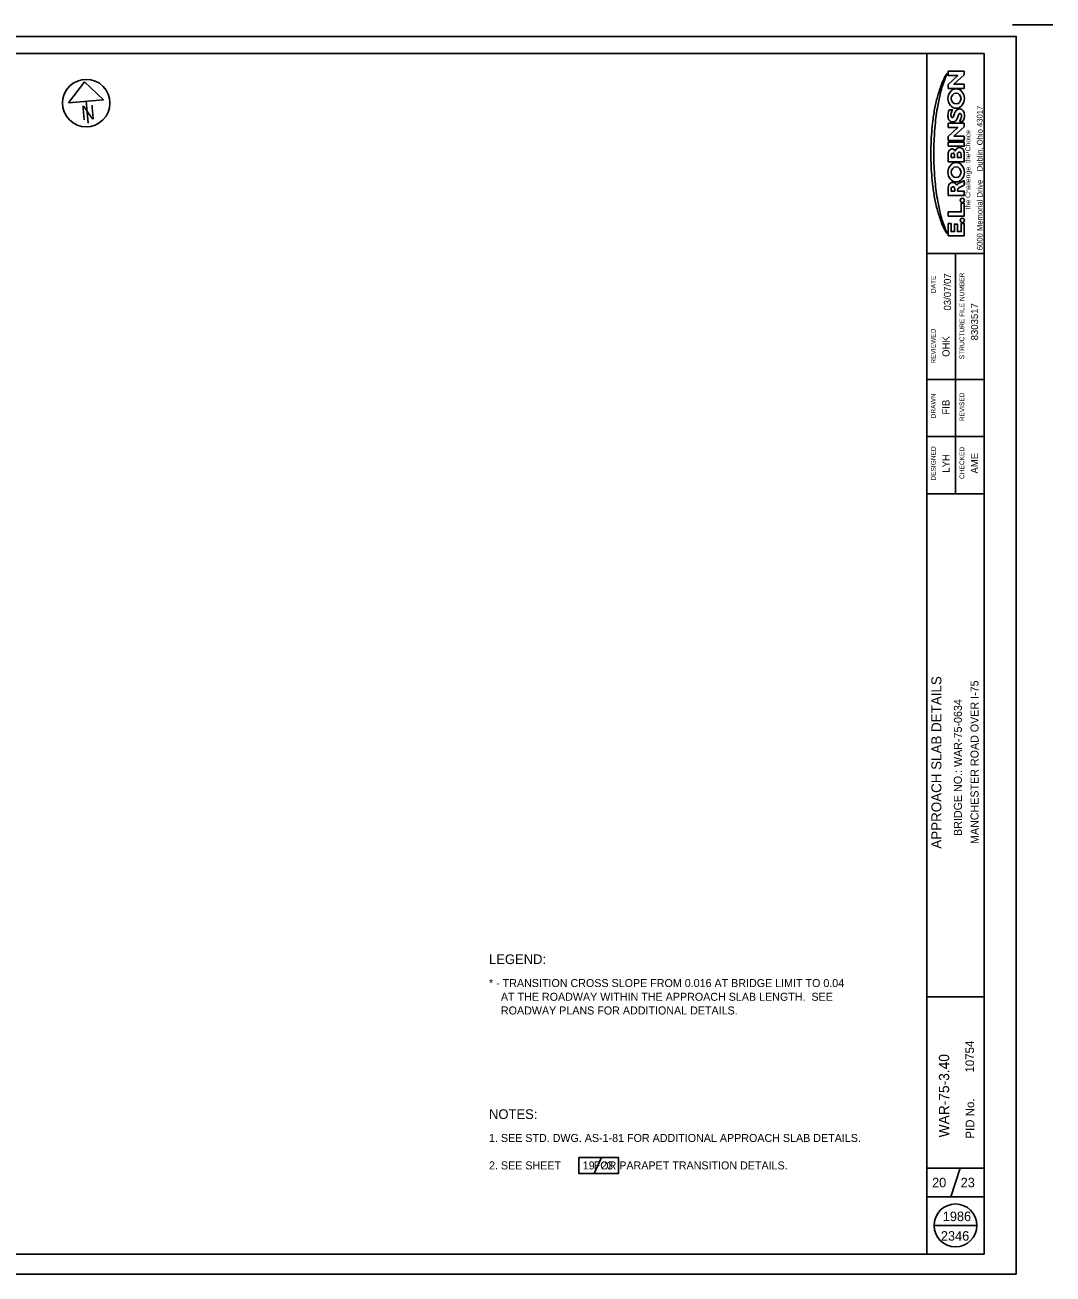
# Model space of a CAD drawing. Extents: x 104.8 to 140.7, y 4.6 to 26.6.
# Drawn here: x 122.74 to 140.72, y 4.7 to 26.55 of the extents above; entities that cross this region are included whole.
import ezdxf

# ---------------------------------------------------------------- set-up
doc = ezdxf.new("R2010")
doc.units = 0
for name, color, linetype in [('BR_P_Gen_Text', 7, 'Continuous'), ('SH_Border', 7, 'Continuous'), ('SH_Cut_Line', 7, 'Continuous'), ('SH_Data', 7, 'Continuous')]:
    doc.layers.add(name, color=color, linetype=linetype)

msp = doc.modelspace()

# ---------------------------------------------------------------- linework, layer by layer
at = {"layer": 'BR_P_Gen_Text'}
for p, q in [((139.143, 24.862), (139.082, 24.862)), ((139.082, 24.862), (139.143, 24.862)), ((138.887, 24.159), (138.887, 24.294)), ((138.938, 24.279), (138.938, 24.234)), ((138.938, 24.234), (138.938, 24.279)), ((139.166, 24.309), (139.166, 24.159)), ((139.166, 24.159), (138.887, 24.159)), ((138.937, 23.689), (138.937, 23.646)), ((138.937, 23.646), (138.937, 23.689)), ((138.937, 23.646), (139.001, 23.646)), ((139.001, 23.646), (138.937, 23.646)), ((139.001, 23.646), (139.001, 23.689)), ((139.001, 23.689), (139.001, 23.646)), ((139.166, 23.749), (139.084, 23.71)), ((139.084, 23.71), (139.166, 23.749)), ((132.824, 6.741), (132.695, 6.463))]:
    msp.add_line(p, q, dxfattribs=at)
for points in [[(139.166, 25.443), (138.887, 25.443), (138.887, 25.512), (139.055, 25.668), (138.887, 25.668), (138.887, 25.743), (139.166, 25.743), (139.166, 25.678), (138.988, 25.517), (139.166, 25.517)], [(139.166, 24.535), (138.887, 24.535), (138.887, 24.604), (139.055, 24.76), (138.887, 24.76), (138.887, 24.834), (139.166, 24.834), (139.166, 24.77), (138.988, 24.609), (139.166, 24.609)], [(138.887, 24.431), (138.887, 24.505), (139.166, 24.505), (139.166, 24.431)], [(138.887, 22.863), (138.887, 23.078), (138.938, 23.078), (138.938, 22.939), (138.996, 22.939), (138.996, 23.07), (139.047, 23.07), (139.047, 22.939), (139.114, 22.939), (139.114, 23.081), (139.166, 23.081), (139.166, 22.863)], [(132.427, 6.741), (133.123, 6.741), (133.123, 6.463), (132.427, 6.463)], [(132.427, 6.741), (133.123, 6.741), (133.123, 6.463), (132.427, 6.463)]]:
    msp.add_lwpolyline(points, close=True, dxfattribs=at)
for points in [[(138.905, 25.07), (138.96, 25.07), (138.949, 25.043)], [(138.949, 25.043), (138.96, 25.07), (138.905, 25.07)], [(139.166, 24.309), (139.166, 24.159), (138.887, 24.159), (138.887, 24.294)], [(138.887, 24.294), (138.887, 24.159), (139.166, 24.159)], [(138.938, 24.234), (138.997, 24.234), (138.997, 24.279)], [(138.997, 24.279), (138.997, 24.234), (138.938, 24.234)], [(139.048, 24.288), (139.048, 24.234), (139.114, 24.234), (139.114, 24.288)], [(139.114, 24.288), (139.114, 24.234), (139.048, 24.234), (139.048, 24.288)], [(139.166, 24.159), (139.166, 24.309)], [(139.101, 23.799), (139.166, 23.831), (139.166, 23.749)], [(139.166, 23.749), (139.166, 23.831), (139.101, 23.799)], [(139.052, 23.668), (139.052, 23.646), (139.166, 23.646), (139.166, 23.571), (138.887, 23.571), (138.887, 23.646), (138.887, 23.71)], [(138.887, 23.71), (138.887, 23.646), (138.887, 23.571), (139.166, 23.571)], [(138.937, 23.689), (138.937, 23.646), (139.001, 23.646), (139.001, 23.689)], [(139.166, 23.571), (139.166, 23.646), (139.052, 23.646), (139.052, 23.668)], [(138.887, 23.207), (138.887, 23.282), (139.114, 23.282), (139.114, 23.434), (139.166, 23.434), (139.166, 23.207), (138.887, 23.207)], [(139.166, 23.434), (139.114, 23.434), (139.114, 23.282), (138.887, 23.282), (138.887, 23.207)], [(138.887, 23.207), (139.166, 23.207), (139.166, 23.434)]]:
    msp.add_lwpolyline(points, dxfattribs=at)
for centre, major_axis, ratio, start_param, end_param in [((140.128, 24.895), (0, 1.685), 0.85, 1.132502, 1.288747), ((140.128, 24.895), (0, 1.685), 0.85, 1.132502, 1.288747), ((139.65, 25.036), (0, 1.141), 0.85, 0.988431, 1.105191), ((139.65, 25.036), (0, 1.141), 0.85, 0.988431, 1.105191), ((100.385, 46.81), (0, 49.953), 0.85, 4.274094, 4.276309), ((100.385, 46.81), (0, 49.953), 0.85, 4.274094, 4.276309), ((139.097, 25.464), (0, 0.363), 0.85, 0.822588, 0.988431), ((139.097, 25.464), (0, 0.363), 0.85, 0.822588, 0.988431), ((141.626, 24.385), (0, 3.52), 0.85, 1.288747, 1.354281), ((141.626, 24.385), (0, 3.52), 0.85, 1.288747, 1.354281), ((141.202, 24.29), (0, 3.112), 0.85, 1.165908, 1.233316), ((141.202, 24.29), (0, 3.112), 0.85, 1.165908, 1.233316), ((139.226, 25.286), (0, 0.583), 0.85, 1.105191, 1.165908), ((139.226, 25.286), (0, 0.583), 0.85, 1.105191, 1.165908), ((140.411, 24.638), (0, 2.119), 0.85, 1.243005, 1.347881), ((140.411, 24.638), (0, 2.119), 0.85, 1.243005, 1.347881), ((142.845, 24.191), (0, 4.963), 0.85, 1.378198, 1.448475), ((142.845, 24.191), (0, 4.963), 0.85, 1.378198, 1.448475), ((139.026, 25.266), (0, -0.0938), 0.910305, 4.71238898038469, 4.712389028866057), ((141.6, 24.368), (0, 3.544), 0.85, 1.360764, 1.426378), ((141.6, 24.368), (0, 3.544), 0.85, 1.360764, 1.426378), ((139.044, 24.97), (0, 0.19), 0.85, 1.320154, 1.737094), ((139.044, 24.97), (0, 0.19), 0.85, 1.320154, 1.737094), ((138.977, 24.957), (0, 0.11), 0.85, 1.737094, 2.325359), ((138.977, 24.957), (0, 0.11), 0.85, 1.737094, 2.325359), ((139.057, 24.967), (0, 0.206), 0.85, 1.108668, 1.320154), ((139.057, 24.967), (0, 0.206), 0.85, 1.108668, 1.320154), ((138.767, 25.137), (0, 0.176), 0.85, 4.250261, 4.3216), ((138.767, 25.137), (0, 0.176), 0.85, 4.250261, 4.3216), ((139.029, 24.979), (0, 0.111), 0.85, 1.456901, 1.818883), ((139.029, 24.979), (0, 0.111), 0.85, 1.456901, 1.818883), ((139.032, 24.979), (0, 0.115), 0.85, 1.297264, 1.456901), ((139.032, 24.979), (0, 0.115), 0.85, 1.297264, 1.456901), ((138.96, 24.959), (0, 0.0279), 0.85, 1.818883, 2.384672), ((138.96, 24.959), (0, 0.0279), 0.85, 1.818883, 2.384672), ((139.099, 24.957), (0, 0.196), 0.85, 1.114999, 1.297264), ((139.099, 24.957), (0, 0.196), 0.85, 1.114999, 1.297264), ((138.956, 24.953), (0, 0.0197), 0.85, 2.384672, 3.137191), ((138.956, 24.953), (0, 0.0197), 0.85, 2.384672, 3.137191), ((138.956, 24.961), (0, 0.0276), 0.85, 3.137191, 4.01614), ((138.956, 24.961), (0, 0.0276), 0.85, 3.137191, 4.01614), ((138.927, 24.989), (0, 0.071), 0.85, 4.01614, 4.175459), ((138.927, 24.989), (0, 0.071), 0.85, 4.01614, 4.175459), ((138.858, 25.037), (0, 0.165), 0.85, 4.175459, 4.396402), ((138.858, 25.037), (0, 0.165), 0.85, 4.175459, 4.396402), ((139.184, 24.912), (0, 0.238), 0.85, 1.030221, 1.254809), ((139.184, 24.912), (0, 0.238), 0.85, 1.030221, 1.254809), ((139.091, 24.977), (0, 0.11), 0.85, 0.486829, 1.030221), ((139.091, 24.977), (0, 0.11), 0.85, 0.486829, 1.030221), ((138.933, 24.982), (0, 0.145), 0.85, 3.971659, 4.353371), ((138.933, 24.982), (0, 0.145), 0.85, 3.971659, 4.353371), ((139.026, 25.266), (0, -0.17), 0.841969, 0, 4.84813681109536e-08), ((139.077, 25.007), (0, 0.0761), 0.85, 0.083326, 0.486829), ((139.077, 25.007), (0, 0.0761), 0.85, 0.083326, 0.486829), ((139.668, 24.657), (0, 0.778), 0.85, 1.164639, 1.211778), ((139.668, 24.657), (0, 0.778), 0.85, 1.164639, 1.211778), ((139.281, 24.853), (0, 0.284), 0.85, 1.063855, 1.164639), ((139.281, 24.853), (0, 0.284), 0.85, 1.063855, 1.164639), ((139.093, 24.976), (0, 0.0304), 0.85, 0.715581, 1.063855), ((139.093, 24.976), (0, 0.0304), 0.85, 0.715581, 1.063855), ((139.083, 24.93), (0, 0.154), 0.85, 6.083659, 6.366511), ((139.083, 24.93), (0, 0.154), 0.85, 6.083659, 6.366511), ((139.094, 24.975), (0, 0.0317), 0.85, 0.212074, 0.715581), ((139.094, 24.975), (0, 0.0317), 0.85, 0.212074, 0.715581), ((139.093, 24.98), (0, 0.026), 0.85, 5.247627, 6.495259), ((139.093, 24.98), (0, 0.026), 0.85, 5.247627, 6.495259), ((138.827, 25.079), (0, 0.37), 0.85, 4.172563, 4.251833), ((138.827, 25.079), (0, 0.37), 0.85, 4.172563, 4.251833), ((139.096, 25.008), (0, 0.0741), 0.85, 5.529173, 6.083659), ((139.096, 25.008), (0, 0.0741), 0.85, 5.529173, 6.083659), ((139.031, 24.961), (0, 0.103), 0.85, 4.251833, 4.86616), ((139.031, 24.961), (0, 0.103), 0.85, 4.251833, 4.86616), ((139.077, 24.969), (0, 0.0483), 0.85, 4.86616, 5.247627), ((139.077, 24.969), (0, 0.0483), 0.85, 4.86616, 5.247627), ((139.076, 24.983), (0, 0.109), 0.85, 4.887723, 5.529173), ((139.076, 24.983), (0, 0.109), 0.85, 4.887723, 5.529174), ((139.022, 24.959), (0, 0.173), 0.85, 4.318356, 4.51081), ((139.022, 24.959), (0, 0.173), 0.85, 4.318356, 4.51081), ((138.996, 24.966), (0, 0.205), 0.85, 4.51081, 4.887723), ((138.996, 24.966), (0, 0.205), 0.85, 4.51081, 4.887723), ((140.18, 24.545), (0, 1.866), 0.85, 1.391456, 1.496401), ((140.18, 24.545), (0, 1.866), 0.85, 1.391456, 1.496401), ((144.443, 24.124), (0, 6.84), 0.85, 1.472392, 1.505619), ((144.443, 24.124), (0, 6.84), 0.85, 1.472392, 1.505619), ((138.956, 24.934), (0, 0.0764), 0.85, 2.325359, 2.878408), ((138.956, 24.934), (0, 0.0764), 0.85, 2.325359, 2.878408), ((138.964, 24.97), (0, 0.113), 0.85, 2.878408, 3.55749), ((138.964, 24.97), (0, 0.113), 0.85, 2.878408, 3.55749), ((138.978, 24.934), (0, 0.0738), 0.85, 3.55749, 3.971659), ((138.978, 24.934), (0, 0.0738), 0.85, 3.55749, 3.971659), ((138.904, 25.025), (0, 0.265), 0.85, 4.050165, 4.172563), ((138.904, 25.025), (0, 0.265), 0.85, 4.050165, 4.172563), ((139.038, 24.951), (0, 0.152), 0.85, 4.087438, 4.318356), ((139.038, 24.951), (0, 0.152), 0.85, 4.087438, 4.318356), ((140.381, 24.444), (0, 2.111), 0.85, 1.456986, 1.558686), ((140.381, 24.444), (0, 2.111), 0.85, 1.456986, 1.558686), ((141.988, 24.313), (0, 3.944), 0.85, 1.505619, 1.553601), ((141.988, 24.313), (0, 3.944), 0.85, 1.505619, 1.553601), ((142.189, 24.251), (0, 4.243), 0.85, 1.519271, 1.558345), ((142.189, 24.251), (0, 4.243), 0.85, 1.519271, 1.558345), ((142.189, 24.357), (0, 4.243), 0.85, 1.583248, 1.622322), ((142.189, 24.357), (0, 4.243), 0.85, 1.583248, 1.622322), ((140.537, 24.342), (0, 2.237), 0.85, 1.553601, 1.587991), ((140.537, 24.342), (0, 2.237), 0.85, 1.553601, 1.587991), ((140.537, 24.265), (0, 2.237), 0.85, 1.553601, 1.587991), ((140.537, 24.265), (0, 2.237), 0.85, 1.553601, 1.587991), ((138.993, 24.292), (0, 0.124), 0.85, 1.228703, 1.558605), ((138.993, 24.292), (0, 0.124), 0.85, 1.228703, 1.558605), ((138.993, 24.292), (0, 0.124), 0.85, 1.228703, 1.558605), ((138.959, 24.303), (0, 0.0833), 0.85, 0.473795, 1.194239), ((138.959, 24.303), (0, 0.0833), 0.85, 0.473795, 1.194239), ((138.959, 24.303), (0, 0.0833), 0.85, 0.473795, 1.194239), ((138.956, 24.317), (0, 0.0696), 0.85, 5.943917, 6.808987), ((138.956, 24.317), (0, 0.0696), 0.85, 5.943917, 6.808987), ((138.956, 24.317), (0, 0.0696), 0.85, 5.943917, 6.808987), ((138.967, 24.277), (0, 0.0337), 0.85, 6.249041, 7.784024), ((138.967, 24.277), (0, 0.0337), 0.85, 6.249041, 7.784024), ((138.968, 24.277), (0, 0.0337), 0.85, 4.782347, 6.317329), ((138.968, 24.277), (0, 0.0337), 0.85, 4.782347, 6.317329), ((138.954, 24.31), (0, 0.0776), 0.85, 5.231996, 5.947796), ((138.954, 24.31), (0, 0.0776), 0.85, 5.231996, 5.947796), ((138.954, 24.31), (0, 0.0776), 0.85, 5.231996, 5.947795), ((139.084, 24.319), (0, 0.0906), 0.85, 0.462144, 1.247207), ((139.084, 24.319), (0, 0.0906), 0.85, 0.462144, 1.247207), ((139.084, 24.319), (0, 0.0906), 0.85, 0.462144, 1.247207), ((139.082, 24.291), (0, 0.0402), 0.85, 0.503186, 1.629765), ((139.082, 24.291), (0, 0.0402), 0.85, 0.503186, 1.629765), ((139.085, 24.311), (0, 0.0982), 0.85, 6.14188, 6.715345), ((139.085, 24.311), (0, 0.0982), 0.85, 6.14188, 6.715345), ((139.085, 24.311), (0, 0.0982), 0.85, 6.14188, 6.715345), ((139.081, 24.295), (0, 0.0358), 0.85, 6.277029, 6.794667), ((139.081, 24.295), (0, 0.0358), 0.85, 6.277029, 6.794667), ((139.081, 24.295), (0, 0.0358), 0.85, 5.771704, 6.289341), ((139.081, 24.295), (0, 0.0358), 0.85, 5.771704, 6.289341), ((139.08, 24.291), (0, 0.0402), 0.85, 4.65342, 5.779999), ((139.08, 24.291), (0, 0.0402), 0.85, 4.65342, 5.779999), ((139.089, 24.32), (0, 0.0885), 0.85, 5.535543, 6.182102), ((139.089, 24.32), (0, 0.0885), 0.85, 5.535543, 6.182102), ((139.089, 24.32), (0, 0.0885), 0.85, 5.535543, 6.182102), ((139.094, 24.324), (0, 0.0818), 0.85, 4.885157, 5.560215), ((139.094, 24.324), (0, 0.0818), 0.85, 4.885157, 5.560215), ((139.094, 24.324), (0, 0.0818), 0.85, 4.885157, 5.560215), ((138.994, 24.302), (0, 0.202), 0.85, 4.750784, 4.89449), ((138.994, 24.302), (0, 0.202), 0.85, 4.750784, 4.89449), ((138.994, 24.302), (0, 0.202), 0.85, 4.750784, 4.89449), ((140.381, 24.164), (0, 2.111), 0.85, 1.582906, 1.684607), ((140.381, 24.164), (0, 2.111), 0.85, 1.582906, 1.684607), ((141.988, 24.295), (0, 3.944), 0.85, 1.587991, 1.635974), ((141.988, 24.295), (0, 3.944), 0.85, 1.587991, 1.635974), ((144.443, 24.483), (0, 6.84), 0.85, 1.635974, 1.669201), ((144.443, 24.483), (0, 6.84), 0.85, 1.635974, 1.669201), ((140.18, 24.063), (0, 1.866), 0.85, 1.645192, 1.750137), ((140.18, 24.063), (0, 1.866), 0.85, 1.645192, 1.750137), ((139.026, 23.977), (0, -0.0938), 0.910305, 4.71238898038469, 4.712389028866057), ((141.6, 24.24), (0, 3.544), 0.85, 1.715214, 1.780828), ((141.6, 24.24), (0, 3.544), 0.85, 1.715214, 1.780828), ((142.845, 24.417), (0, 4.963), 0.85, 1.693118, 1.763395), ((142.845, 24.417), (0, 4.963), 0.85, 1.693118, 1.763395), ((138.963, 23.709), (0, 0.0895), 0.85, 0.482355, 1.561069), ((138.963, 23.709), (0, 0.0895), 0.85, 0.482355, 1.561069), ((138.968, 23.7), (0, 0.1), 0.85, 6.102437, 6.781247), ((138.968, 23.7), (0, 0.1), 0.85, 6.102437, 6.781247), ((138.977, 23.685), (0, 0.0467), 0.85, 1.002734, 1.50285), ((138.977, 23.685), (0, 0.0467), 0.85, 1.002734, 1.50285), ((138.977, 23.685), (0, 0.0467), 0.85, 1.002734, 1.50285), ((138.968, 23.688), (0, 0.0365), 0.85, 6.259044, 7.205975), ((138.968, 23.688), (0, 0.0365), 0.85, 6.259044, 7.205975), ((138.968, 23.688), (0, 0.0365), 0.85, 6.259044, 7.205975), ((138.97, 23.688), (0, 0.0365), 0.85, 5.360396, 6.307326), ((138.97, 23.688), (0, 0.0365), 0.85, 5.360396, 6.307326), ((138.97, 23.688), (0, 0.0365), 0.85, 5.360396, 6.307326), ((138.967, 23.713), (0, 0.0881), 0.85, 5.152888, 6.061538), ((138.967, 23.713), (0, 0.0881), 0.85, 5.152888, 6.061538), ((138.961, 23.685), (0, 0.0467), 0.85, 4.780335, 5.280452), ((138.961, 23.685), (0, 0.0467), 0.85, 4.780335, 5.280452), ((138.961, 23.685), (0, 0.0467), 0.85, 4.780335, 5.280452), ((139.026, 23.977), (0, -0.17), 0.841969, 0, 4.84813681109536e-08), ((139.085, 23.714), (0, 0.069), 0.85, 0.463729, 1.012038), ((139.085, 23.714), (0, 0.069), 0.85, 0.463729, 1.012038), ((139.078, 23.669), (0, 0.0303), 0.85, 0.984544, 1.600686), ((139.078, 23.669), (0, 0.0303), 0.85, 0.984544, 1.600686), ((139.102, 23.649), (0, 0.0643), 0.85, 0.32473, 0.965239), ((139.102, 23.649), (0, 0.0643), 0.85, 0.32473, 0.965239), ((139.192, 23.502), (0, 0.316), 0.85, 0.346308, 0.520291), ((139.192, 23.502), (0, 0.316), 0.85, 0.346308, 0.520291), ((140.411, 23.969), (0, 2.119), 0.85, 1.793712, 1.898588), ((140.411, 23.969), (0, 2.119), 0.85, 1.793712, 1.898588), ((141.626, 24.223), (0, 3.52), 0.85, 1.787312, 1.852845), ((141.626, 24.223), (0, 3.52), 0.85, 1.787312, 1.852845), ((139.134, 23.484), (0, -0.0377), 0.965476, 4.71238898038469, 4.712389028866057), ((141.202, 24.318), (0, 3.112), 0.85, 1.908276, 1.975684), ((141.202, 24.318), (0, 3.112), 0.85, 1.908276, 1.975684), ((140.128, 23.712), (0, 1.685), 0.85, 1.852845, 2.009091), ((140.128, 23.712), (0, 1.685), 0.85, 1.852845, 2.009091), ((139.226, 23.321), (0, 0.583), 0.85, 1.975684, 2.036401), ((139.226, 23.321), (0, 0.583), 0.85, 1.975684, 2.036401), ((139.65, 23.572), (0, 1.141), 0.85, 2.036401, 2.153161), ((139.65, 23.572), (0, 1.141), 0.85, 2.036401, 2.153161), ((100.385, 1.798), (0, 49.953), 0.85, 5.148469, 5.150684), ((100.385, 1.798), (0, 49.953), 0.85, 5.148469, 5.150684), ((139.097, 23.144), (0, 0.363), 0.85, 2.153161, 2.319004), ((139.097, 23.144), (0, 0.363), 0.85, 2.153161, 2.319004), ((139.134, 23.134), (0, -0.0377), 0.965476, 4.71238898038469, 4.712389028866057)]:
    msp.add_ellipse(centre, major_axis=major_axis, ratio=ratio, start_param=start_param, end_param=end_param, dxfattribs=at)
for centre, major_axis, ratio in [((139.026, 25.266), (0, -0.17), 0.841969), ((139.026, 25.266), (0, -0.17), 0.841969), ((139.026, 25.266), (0, -0.0938), 0.910305), ((139.026, 25.266), (0, -0.0938), 0.910305), ((139.026, 23.977), (0, -0.17), 0.841969), ((139.026, 23.977), (0, -0.17), 0.841969), ((139.026, 23.977), (0, -0.0938), 0.910305), ((139.026, 23.977), (0, -0.0938), 0.910305), ((139.134, 23.484), (0, -0.0377), 0.965476), ((139.134, 23.134), (0, -0.0377), 0.965476), ((139.134, 23.134), (0, -0.0377), 0.965476)]:
    msp.add_ellipse(centre, major_axis=major_axis, ratio=ratio, dxfattribs=at)
at = {"layer": 'SH_Border'}
for p, q in [((138.514, 5.053), (138.514, 26.053)), ((138.514, 22.553), (139.514, 22.553)), ((139.014, 18.353), (139.014, 22.553)), ((138.514, 20.353), (139.514, 20.353)), ((138.514, 19.353), (139.514, 19.353)), ((138.514, 18.353), (139.514, 18.353)), ((138.514, 9.553), (139.514, 9.553)), ((138.514, 6.553), (139.514, 6.553)), ((138.931, 6.053), (139.097, 6.553)), ((138.514, 6.053), (139.514, 6.053))]:
    msp.add_line(p, q, dxfattribs=at)
msp.add_lwpolyline([(108.014, 26.053), (139.514, 26.053), (139.514, 5.053), (108.014, 5.053)], close=True, dxfattribs=at)
at = {"layer": 'SH_Cut_Line'}
msp.add_line((140.014, 26.553), (140.719, 26.553), dxfattribs=at)
msp.add_lwpolyline([(140.077, 4.703), (106.077, 4.703), (106.077, 26.353), (140.077, 26.353)], close=True, dxfattribs=at)
at = {"layer": 'SH_Data'}
for p, q in [((123.784, 25.559), (123.507, 25.192)), ((124.12, 25.246), (123.784, 25.559)), ((123.507, 25.192), (124.12, 25.246)), ((123.813, 25.219), (123.847, 24.834)), ((138.639, 5.553), (139.389, 5.553))]:
    msp.add_line(p, q, dxfattribs=at)
msp.add_circle((139.014, 5.553), 0.375, dxfattribs=at)
msp.add_arc((123.816, 25.187), 0.415, 134.748, 134.7315, dxfattribs=at)

# ---------------------------------------------------------------- texts
at = {"layer": 'BR_P_Gen_Text'}
for s, height, p in [('6000 Memorial Drive    Dublin, Ohio 43017', 0.1, (139.488, 22.613)), ('the Challenge. the Choice', 0.0875, (139.275, 23.326))]:
    msp.add_text(s, height=height, rotation=90, dxfattribs=at).set_placement(p)
for s, height, p in [('LEGEND:', 0.17, (130.858, 10.125)), ('* - TRANSITION CROSS SLOPE FROM 0.016 AT BRIDGE LIMIT TO 0.04', 0.14, (130.858, 9.723)), ('    AT THE ROADWAY WITHIN THE APPROACH SLAB LENGTH.  SEE', 0.14, (130.858, 9.483)), ('    ROADWAY PLANS FOR ADDITIONAL DETAILS.', 0.14, (130.858, 9.243)), ('NOTES:', 0.17, (130.858, 7.415)), ('1. SEE STD. DWG. AS-1-81 FOR ADDITIONAL APPROACH SLAB DETAILS.', 0.14, (130.858, 7.013)), ('2. SEE SHEET           FOR PARAPET TRANSITION DETAILS.', 0.14, (130.858, 6.533)), ('19', 0.14, (132.497, 6.532)), ('23', 0.14, (132.818, 6.532))]:
    msp.add_text(s, height=height, dxfattribs=at).set_placement(p)
at = {"layer": 'SH_Data'}
for s, height, rotation, p in [('N', 0.25, 4.9682, (123.738, 24.887)), ('.', 0.125, 90, (138.997, 24.307)), ("'", 0.125, 90, (139.331, 24.307)), ('DATE', 0.0833, 90, (138.668, 21.862)), ('03/07/07', 0.125, 90, (138.936, 21.558)), ('STRUCTURE FILE NUMBER', 0.0833, 90, (139.168, 20.706)), ('8303517', 0.125, 90, (139.41, 21.036)), ('REVIEWED', 0.0833, 90, (138.668, 20.628)), ('OHK', 0.125, 90, (138.91, 20.747)), ('REVISED', 0.0833, 90, (139.168, 19.619)), ('DRAWN', 0.0833, 90, (138.668, 19.671)), ('FIB', 0.125, 90, (138.91, 19.738)), ('DESIGNED', 0.0833, 90, (138.668, 18.582)), ('LYH', 0.125, 90, (138.91, 18.72)), ('CHECKED', 0.0833, 90, (139.168, 18.61)), ('AME', 0.125, 90, (139.41, 18.705)), ('APPROACH SLAB DETAILS', 0.175, 90, (138.768, 12.144)), ('MANCHESTER ROAD OVER I-75', 0.14, 90, (139.417, 12.226)), ('BRIDGE NO.: WAR-75-0634', 0.14, 90, (139.126, 12.366)), (' 10754', 0.15, 90, (139.339, 8.171)), ('WAR-75-3.40', 0.18, 90, (138.904, 7.093)), ('PID No.', 0.15, 90, (139.342, 7.072))]:
    msp.add_text(s, height=height, rotation=rotation, dxfattribs=at).set_placement(p)
for s, p in [(' 20', (138.543, 6.22)), (' 23', (139.043, 6.22)), ('1986', (138.792, 5.628)), ('2346', (138.759, 5.286))]:
    msp.add_text(s, height=0.1666, dxfattribs=at).set_placement(p)

doc.saveas('drawing.dxf')
